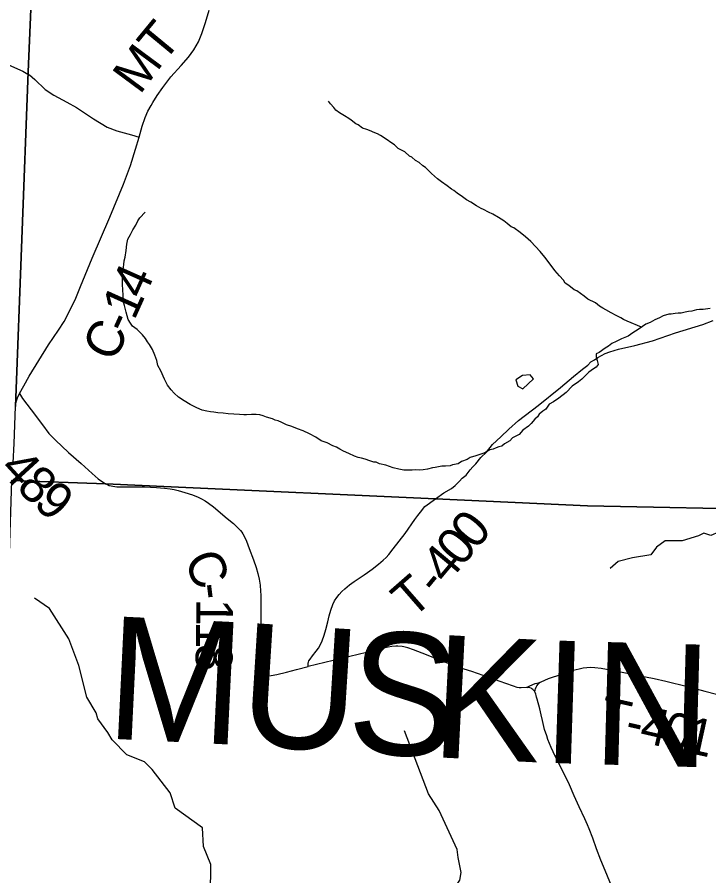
# Model space of a CAD drawing. Extents: x 0 to 34, y 0 to 22.
# Drawn here: x 26.261 to 27.33, y 17.319 to 18.646 of the extents above; entities that cross this region are included whole.
import ezdxf

# ---------------------------------------------------------------- set-up
doc = ezdxf.new("R2010")
doc.units = 0
for name, color, linetype in [('GM_X_Adjacent_County', 7, 'Continuous'), ('GM_X_Adjacent_County_Text', 7, 'Continuous'), ('GM_X_County', 7, 'Continuous'), ('GM_X_County_Road', 7, 'Continuous'), ('GM_X_County_Road_Text', 7, 'Continuous'), ('GM_X_Minor_Lake', 7, 'Continuous'), ('GM_X_Minor_River', 7, 'Continuous'), ('GM_X_Township', 7, 'Continuous'), ('GM_X_Township_Road', 7, 'Continuous'), ('GM_X_Township_Road_Text', 7, 'Continuous')]:
    doc.layers.add(name, color=color, linetype=linetype)

msp = doc.modelspace()

# ---------------------------------------------------------------- linework, layer by layer
at = {"layer": 'GM_X_Adjacent_County'}
for points in [[(29.1279, 17.8574), (28.6324, 17.8677), (28.1264, 17.8728), (27.8903, 17.8826), (27.7531, 17.8783), (27.1422, 17.8906), (26.9072, 17.9017), (26.4988, 17.9198), (26.3979, 17.9244), (26.2521, 17.9299)], [(26.2521, 17.9299), (26.3979, 17.9244), (26.4988, 17.9198), (26.9072, 17.9017), (27.1422, 17.8906), (27.7531, 17.8783), (27.8903, 17.8826), (28.1264, 17.8728), (28.6324, 17.8677), (29.1279, 17.8574)]]:
    msp.add_lwpolyline(points, dxfattribs=at)
at = {"layer": 'GM_X_County'}
for points in [[(26.2521, 17.9299), (26.3979, 17.9244), (26.4988, 17.9198), (26.9072, 17.9017), (27.1422, 17.8906), (27.7531, 17.8783), (27.8903, 17.8826), (28.1264, 17.8728), (28.6324, 17.8677), (29.1279, 17.8574)], [(29.1279, 17.8574), (28.6324, 17.8677), (28.1264, 17.8728), (27.8903, 17.8826), (27.7531, 17.8783), (27.1422, 17.8906), (26.9072, 17.9017), (26.4988, 17.9198), (26.3979, 17.9244), (26.2521, 17.9299)]]:
    msp.add_lwpolyline(points, dxfattribs=at)
at = {"layer": 'GM_X_County_Road'}
for points in [[(26.2645, 18.0641), (26.2708, 18.0762), (26.2794, 18.0911), (26.3092, 18.1395), (26.3247, 18.1621), (26.3335, 18.1754), (26.3418, 18.1917), (26.3512, 18.2118), (26.3583, 18.2295), (26.3766, 18.2737), (26.404, 18.337), (26.4252, 18.3876), (26.4358, 18.4166), (26.4436, 18.4418), (26.4491, 18.4603), (26.454, 18.4777), (26.4585, 18.4908), (26.4624, 18.5005), (26.4677, 18.5096), (26.4706, 18.5139), (26.4771, 18.5249), (26.4856, 18.5372), (26.4984, 18.5535), (26.5141, 18.5715), (26.5256, 18.5842), (26.5337, 18.5956), (26.5409, 18.6079), (26.5462, 18.6205), (26.552, 18.6379), (26.5576, 18.6567)], [(26.2547, 17.9571), (26.2561, 17.9871), (26.2579, 18.0444), (26.2593, 18.0513), (26.2611, 18.0574), (26.2645, 18.0641)], [(26.2645, 18.0641), (26.2689, 18.0566), (26.2824, 18.0389), (26.2998, 18.016), (26.3095, 18.0024), (26.3197, 17.9919), (26.34, 17.9732), (26.3594, 17.9563), (26.3765, 17.9405), (26.3858, 17.9324), (26.397, 17.9245)], [(26.397, 17.9245), (26.4001, 17.9234), (26.4029, 17.9223), (26.4058, 17.9215), (26.4087, 17.9209), (26.4147, 17.9202), (26.4239, 17.9199), (26.4484, 17.92), (26.4577, 17.9199), (26.4669, 17.9196), (26.4761, 17.9191), (26.4883, 17.9182), (26.4974, 17.917), (26.5035, 17.9159), (26.5096, 17.9145), (26.5197, 17.9115), (26.5315, 17.9076), (26.5402, 17.9041), (26.5458, 17.9015), (26.5513, 17.8984), (26.5565, 17.8949), (26.5639, 17.8892), (26.5853, 17.8713), (26.5948, 17.8633), (26.5994, 17.8592), (26.6039, 17.8548), (26.6059, 17.8524), (26.6078, 17.85), (26.6095, 17.8474), (26.6126, 17.8419), (26.615, 17.8358), (26.6194, 17.8247), (26.626, 17.8071), (26.63, 17.7953), (26.6326, 17.7863), (26.6347, 17.7772), (26.6361, 17.7679), (26.637, 17.7586), (26.6372, 17.7524), (26.6373, 17.743), (26.6375, 17.7369), (26.6374, 17.7245), (26.6373, 17.7121), (26.6368, 17.6998), (26.6364, 17.6905), (26.6362, 17.6813), (26.6357, 17.6657), (26.6351, 17.6534), (26.635, 17.6441), (26.6352, 17.6411), (26.6355, 17.6382), (26.636, 17.6363), (26.6366, 17.6352), (26.6379, 17.6334), (26.6399, 17.6313), (26.6409, 17.6305), (26.642, 17.63), (26.6444, 17.629), (26.6472, 17.6284), (26.6502, 17.628), (26.6532, 17.6283), (26.6622, 17.6301), (26.6772, 17.6337), (26.6922, 17.6377), (26.7104, 17.6423)]]:
    msp.add_lwpolyline(points, dxfattribs=at)
at = {"layer": 'GM_X_Minor_Lake'}
for points in [[(27.0589, 18.0872), (27.0535, 18.0933), (27.0418, 18.0921), (27.0316, 18.0853)], [(27.0316, 18.0853), (27.0343, 18.0754), (27.0422, 18.0716), (27.0589, 18.0872)]]:
    msp.add_lwpolyline(points, dxfattribs=at)
at = {"layer": 'GM_X_Minor_River'}
for points in [[(27.2259, 18.1667), (27.2037, 18.1763), (27.198, 18.1789), (27.1939, 18.1812), (27.1866, 18.1846), (27.1787, 18.1891), (27.1703, 18.1937), (27.1658, 18.1963), (27.1608, 18.1994), (27.1548, 18.2043), (27.1426, 18.2103), (27.1373, 18.2149), (27.1316, 18.219), (27.1255, 18.2232), (27.1217, 18.2247), (27.1134, 18.2311), (27.1077, 18.2349), (27.105, 18.2394), (27.0989, 18.2463), (27.0917, 18.2542), (27.0845, 18.2641), (27.0765, 18.2751), (27.0689, 18.2838), (27.062, 18.2917), (27.0548, 18.2993), (27.0465, 18.3065), (27.0381, 18.3133), (27.0282, 18.3201), (27.0244, 18.322), (27.018, 18.3269), (27.0127, 18.3311), (27.0047, 18.3364), (26.996, 18.3413), (26.9891, 18.3447), (26.9816, 18.3488), (26.9778, 18.3503), (26.9705, 18.3545), (26.9618, 18.3602), (26.9554, 18.3636), (26.9489, 18.3685), (26.9409, 18.3738), (26.9356, 18.3783), (26.9318, 18.3802), (26.9254, 18.3851), (26.9163, 18.3912), (26.9106, 18.3961), (26.9011, 18.4041), (26.8916, 18.4135), (26.8878, 18.4162), (26.8821, 18.4211), (26.8764, 18.4245), (26.8707, 18.4294), (26.8669, 18.4309), (26.8597, 18.4377), (26.8494, 18.443), (26.8441, 18.4487), (26.8399, 18.451), (26.8312, 18.4574), (26.8224, 18.4631), (26.8175, 18.4654), (26.8133, 18.4672), (26.805, 18.471), (26.8012, 18.4721), (26.7944, 18.4744), (26.7879, 18.4793), (26.7841, 18.4812), (26.7769, 18.4869), (26.7731, 18.4892), (26.7667, 18.4933), (26.7587, 18.4982), (26.753, 18.5024), (26.7499, 18.5062), (26.745, 18.5122), (26.742, 18.516)], [(26.8948, 17.9472), (26.888, 17.9461), (26.8823, 17.9457), (26.877, 17.9461), (26.8713, 17.9457), (26.8638, 17.9457), (26.8585, 17.946), (26.8505, 17.9475), (26.8418, 17.9494), (26.8304, 17.9536), (26.8209, 17.9558), (26.8156, 17.9581), (26.8118, 17.9584), (26.8057, 17.96), (26.7985, 17.9626), (26.7929, 17.9641), (26.7879, 17.9652), (26.7822, 17.9675), (26.7735, 17.9716), (26.7652, 17.975), (26.7595, 17.9784), (26.7542, 17.9811), (26.7488, 17.9834), (26.7397, 17.9879), (26.7306, 17.9913), (26.7223, 17.997), (26.7124, 18.0019), (26.7025, 18.0064), (26.6942, 18.0098), (26.6851, 18.0132), (26.6771, 18.0158), (26.6699, 18.0196), (26.6639, 18.0219), (26.6593, 18.023), (26.6551, 18.0249), (26.646, 18.0279), (26.6407, 18.0298), (26.6358, 18.0313), (26.6301, 18.0317), (26.6229, 18.0317), (26.6149, 18.0313), (26.6112, 18.0313), (26.6043, 18.0316), (26.5956, 18.0324), (26.5869, 18.0327), (26.5793, 18.0339), (26.571, 18.0346), (26.5649, 18.0353), (26.5596, 18.0361), (26.5539, 18.0372), (26.5467, 18.0387), (26.5384, 18.0421), (26.5281, 18.0474), (26.5186, 18.0531), (26.5099, 18.0588), (26.5034, 18.0648), (26.4985, 18.0697), (26.4932, 18.0773), (26.4882, 18.0864), (26.4829, 18.0993), (26.4783, 18.1076), (26.4764, 18.1152), (26.4733, 18.1236), (26.4699, 18.1323), (26.4653, 18.1402), (26.4623, 18.144), (26.4589, 18.1493), (26.4543, 18.155), (26.4459, 18.1633), (26.4387, 18.1683), (26.4357, 18.1728), (26.4322, 18.1789), (26.4292, 18.1902), (26.4265, 18.2001), (26.425, 18.2054), (26.4246, 18.2096), (26.4246, 18.216), (26.4238, 18.2248), (26.4234, 18.2324), (26.4233, 18.246), (26.4237, 18.2506), (26.4241, 18.2544), (26.4252, 18.2593), (26.4256, 18.2638), (26.4263, 18.2695), (26.4274, 18.2752), (26.4293, 18.2851), (26.4304, 18.295), (26.4319, 18.3026), (26.4356, 18.3102), (26.4394, 18.3174), (26.4439, 18.3246), (26.447, 18.331), (26.4504, 18.3356), (26.4587, 18.3447)], [(27.3317, 18.1955), (27.3208, 18.194), (27.3151, 18.194), (27.3109, 18.1936), (27.3033, 18.1913), (27.2984, 18.1909), (27.2931, 18.1901), (27.287, 18.1886), (27.2821, 18.1882), (27.2776, 18.1878), (27.2715, 18.1871), (27.2677, 18.1867), (27.2594, 18.1844), (27.2537, 18.181), (27.2462, 18.1779), (27.2393, 18.1741), (27.2325, 18.1714), (27.2272, 18.1676), (27.2204, 18.1631), (27.2125, 18.1581), (27.2053, 18.1528), (27.1947, 18.1486), (27.1864, 18.1444), (27.18, 18.1417), (27.1747, 18.1375), (27.1694, 18.1345), (27.1603, 18.1276), (27.1558, 18.1254), (27.1554, 18.1212), (27.1569, 18.1151), (27.1585, 18.109), (27.1558, 18.1052), (27.1513, 18.1022), (27.1445, 18.0973), (27.1335, 18.0862), (27.1282, 18.0824), (27.1184, 18.0756), (27.1093, 18.0657), (27.098, 18.0573), (27.0897, 18.0516), (27.0829, 18.0478), (27.0776, 18.0402), (27.0734, 18.0368), (27.0674, 18.0322), (27.0647, 18.0284), (27.0609, 18.0246), (27.0553, 18.0181), (27.0511, 18.014), (27.0424, 18.0075), (27.0364, 18.0007), (27.0265, 17.9957), (27.022, 17.9911), (27.0141, 17.9866), (27.0099, 17.9831), (27.0054, 17.982), (27.0012, 17.9801), (26.9963, 17.9782), (26.991, 17.977), (26.9834, 17.9725), (26.9759, 17.9698), (26.9694, 17.9679), (26.9611, 17.9656), (26.9562, 17.9622), (26.9475, 17.9591), (26.9422, 17.9557), (26.9338, 17.9538), (26.9297, 17.9526), (26.9225, 17.9522), (26.9168, 17.9522), (26.9066, 17.9499), (26.9024, 17.9492), (26.8948, 17.9472)], [(27.365, 17.8814), (27.3615, 17.8687), (27.3563, 17.8549), (27.3329, 17.8446), (27.3218, 17.8486), (27.314, 17.8445), (27.2886, 17.8365), (27.2621, 17.8368), (27.2489, 17.8269), (27.2403, 17.8151), (27.2119, 17.8104), (27.1896, 17.8046), (27.1772, 17.794)], [(26.5597, 17.2892), (26.5602, 17.3362), (26.5488, 17.3643), (26.5471, 17.3927), (26.505, 17.4233), (26.4973, 17.4468), (26.4695, 17.4831), (26.4573, 17.4948), (26.43, 17.5057), (26.4076, 17.5288), (26.4007, 17.5402), (26.3855, 17.5614), (26.3828, 17.5708), (26.3683, 17.5951), (26.356, 17.644), (26.3407, 17.6853), (26.3106, 17.7322), (26.2874, 17.7477)], [(26.8399, 16.9945), (26.8418, 17.0014), (26.8315, 17.0177), (26.8303, 17.0374), (26.8352, 17.0469), (26.8487, 17.0595), (26.8668, 17.0986), (26.8869, 17.1662), (26.8948, 17.1887), (26.899, 17.2539), (26.9043, 17.2638), (26.9276, 17.2863), (26.9449, 17.3118), (26.9468, 17.3239), (26.9425, 17.347), (26.9406, 17.3595), (26.9127, 17.4198), (26.8967, 17.4455), (26.8591, 17.5429)]]:
    msp.add_lwpolyline(points, dxfattribs=at)
at = {"layer": 'GM_X_Township'}
for points in [[(26.2579, 18.0444), (26.2775, 18.5614), (26.3204, 19.5672), (26.3254, 19.7889), (26.3235, 19.7961), (26.3228, 19.8045), (26.3228, 19.8154), (26.3238, 19.8473), (26.3245, 19.8669), (26.325, 19.9211), (26.326, 19.9813), (26.3403, 20.3674), (26.341, 20.3982), (26.344, 20.4298), (26.3517, 20.745), (26.352, 20.7571), (26.3529, 20.7844), (26.3538, 20.8148), (26.354, 20.8204), (26.3551, 20.8572), (26.3564, 20.9)], [(26.3564, 20.9), (26.3551, 20.8572), (26.354, 20.8204), (26.3538, 20.8148), (26.3529, 20.7844), (26.352, 20.7571), (26.3517, 20.745), (26.344, 20.4298), (26.341, 20.3982), (26.3403, 20.3674), (26.326, 19.9813), (26.325, 19.9211), (26.3245, 19.8669), (26.3238, 19.8473), (26.3228, 19.8154), (26.3228, 19.8045), (26.3235, 19.7961), (26.3254, 19.7889), (26.3204, 19.5672), (26.2775, 18.5614), (26.2579, 18.0444)], [(30.8167, 17.8174), (30.1304, 17.8301), (29.8296, 17.8449), (29.1279, 17.8574), (28.6324, 17.8677), (28.1264, 17.8728), (27.8903, 17.8826), (27.7531, 17.8783), (27.1422, 17.8906), (26.9072, 17.9017), (26.4988, 17.9198), (26.3979, 17.9244), (26.2521, 17.9299), (26.228, 17.2045)], [(26.2521, 17.9299), (26.3979, 17.9244), (26.4988, 17.9198), (26.9072, 17.9017), (27.1422, 17.8906), (27.7531, 17.8783), (27.8903, 17.8826), (28.1264, 17.8728), (28.6324, 17.8677), (29.1279, 17.8574)]]:
    msp.add_lwpolyline(points, dxfattribs=at)
at = {"layer": 'GM_X_Township_Road'}
for points in [[(26.2471, 18.5723), (26.2695, 18.5625), (26.2773, 18.5581), (26.2799, 18.5566), (26.2881, 18.5497)], [(26.2881, 18.5497), (26.2882, 18.5497), (26.3041, 18.5344), (26.3171, 18.5253), (26.3374, 18.5144), (26.3524, 18.5062), (26.3645, 18.4981), (26.3784, 18.4886), (26.3999, 18.476), (26.4146, 18.4702), (26.4375, 18.464), (26.4491, 18.4603)], [(26.9072, 17.9017), (26.9204, 17.9108), (26.9322, 17.9173), (26.9376, 17.9222), (26.9445, 17.9287), (26.9487, 17.9332), (26.9547, 17.938), (26.9611, 17.9464), (26.9651, 17.9511), (26.9698, 17.9558), (26.9775, 17.9655), (26.986, 17.9737), (26.9956, 17.9854), (27.0083, 17.9975), (27.0207, 18.0092), (27.0356, 18.0224), (27.0657, 18.0455), (27.1004, 18.0733), (27.1205, 18.0907), (27.1347, 18.1021), (27.1429, 18.1083), (27.1476, 18.113), (27.1528, 18.1162), (27.1583, 18.1197), (27.1638, 18.1229), (27.1695, 18.1262), (27.1767, 18.1289), (27.1901, 18.1329), (27.2154, 18.1383), (27.2427, 18.1455), (27.278, 18.158), (27.3207, 18.1711), (27.3363, 18.1771)], [(26.7104, 17.6423), (26.7103, 17.6462), (26.7104, 17.6478), (26.7109, 17.6492), (26.7117, 17.6513), (26.7134, 17.6537), (26.7171, 17.6586), (26.7228, 17.6659), (26.7263, 17.6709), (26.7293, 17.6763), (26.7319, 17.6819), (26.7351, 17.6906), (26.7378, 17.6994), (26.7408, 17.7114), (26.7429, 17.7204), (26.7457, 17.7292), (26.7488, 17.7379), (26.7514, 17.7436), (26.7546, 17.7489), (26.7583, 17.7538), (26.7625, 17.7583), (26.7671, 17.7625), (26.7743, 17.7683), (26.7818, 17.7737), (26.7971, 17.784), (26.8021, 17.7875), (26.8096, 17.793), (26.8194, 17.8005), (26.8265, 17.8065), (26.8309, 17.8109), (26.835, 17.8155), (26.8416, 17.8241), (26.8604, 17.8481), (26.8754, 17.8697), (26.88, 17.8756), (26.8841, 17.8808), (26.8909, 17.8896), (26.9072, 17.9017)], [(27.0484, 17.6098), (27.048, 17.6098), (27.0397, 17.6093), (27.0366, 17.6095), (27.0336, 17.61), (27.0276, 17.6117), (27.0159, 17.6158), (26.9633, 17.6344), (26.9515, 17.6383), (26.9339, 17.6444), (26.9136, 17.6522), (26.8935, 17.6602), (26.8733, 17.6683), (26.8645, 17.6713), (26.8585, 17.6729), (26.8555, 17.6734), (26.8493, 17.6738), (26.8462, 17.6737), (26.84, 17.6731), (26.8339, 17.672), (26.8248, 17.67), (26.8008, 17.6638), (26.7104, 17.6423)], [(27.0689, 17.618), (27.0705, 17.6187), (27.0819, 17.6235), (27.1025, 17.6306), (27.1202, 17.6364), (27.1292, 17.6389), (27.1353, 17.6401), (27.1414, 17.6409), (27.1476, 17.6411), (27.1538, 17.6408), (27.1631, 17.6397), (27.1905, 17.6345), (27.221, 17.6284), (27.2453, 17.6237), (27.2635, 17.6196), (27.2966, 17.6114), (27.3237, 17.6043), (27.3417, 17.5996)], [(27.0484, 17.6098), (27.0502, 17.611), (27.0519, 17.6118), (27.0533, 17.6124), (27.0615, 17.6158), (27.0639, 17.6165), (27.0664, 17.6172), (27.0689, 17.618)], [(27.0608, 17.603), (27.0611, 17.6053), (27.0613, 17.6067), (27.0616, 17.6078), (27.0628, 17.6106), (27.0639, 17.6124), (27.0657, 17.6149), (27.0669, 17.6162), (27.0677, 17.6169), (27.0689, 17.618)], [(27.0608, 17.603), (27.0601, 17.6042), (27.0589, 17.6057), (27.0577, 17.6068), (27.0562, 17.6078), (27.0549, 17.6086), (27.0529, 17.6093), (27.0509, 17.6098), (27.0484, 17.6098)], [(27.1777, 17.3067), (27.172, 17.3209), (27.1626, 17.3429), (27.1562, 17.3605), (27.1504, 17.3768), (27.1448, 17.3914), (27.1424, 17.3976), (27.138, 17.407), (27.1292, 17.4254), (27.1217, 17.4424), (27.1143, 17.4595), (27.1077, 17.4735), (27.0921, 17.5036), (27.086, 17.5172), (27.081, 17.5294), (27.0792, 17.5351), (27.076, 17.5447), (27.0727, 17.5588), (27.0705, 17.5678), (27.0684, 17.5768), (27.0644, 17.5918), (27.0635, 17.5949), (27.0628, 17.5974), (27.0622, 17.5994), (27.0613, 17.602), (27.0608, 17.603)]]:
    msp.add_lwpolyline(points, dxfattribs=at)

# ---------------------------------------------------------------- texts
at = {"layer": 'GM_X_Adjacent_County_Text'}
for s, rotation, p in [('M', 357.2115, (26.3958, 17.5311)), ('U', 356.4278, (26.6007, 17.5211)), ('S', 356.4112, (26.7679, 17.5107)), ('K', 357.0853, (26.8984, 17.5025)), ('I', 358.1377, (27.0695, 17.4938)), ('N', 358.4214, (27.148, 17.4913))]:
    msp.add_text(s, height=0.1894, rotation=rotation, dxfattribs=at).set_placement(p)
at = {"layer": 'GM_X_County_Road_Text'}
for s, rotation, p in [('T', 50.454, (26.4865, 18.5738)), ('M', 53.4916, (26.4503, 18.5249)), ('4', 65.8802, (26.4561, 18.2081)), ('1', 65.7626, (26.4416, 18.1761)), ('-', 65.4829, (26.4318, 18.1546)), ('C', 62.9462, (26.4094, 18.1105)), ('4', 312.5205, (26.2311, 17.9463)), ('8', 316.1886, (26.2575, 17.9176)), ('9', 317.633, (26.2839, 17.8923)), ('C', 293.1489, (26.5178, 17.8075)), ('-', 276.9798, (26.5351, 17.7687)), ('1', 269.3182, (26.5378, 17.7475)), ('1', 269.1881, (26.5374, 17.7125)), ('8', 269.1777, (26.5369, 17.6776))]:
    msp.add_text(s, height=0.0568, rotation=rotation, dxfattribs=at).set_placement(p)
at = {"layer": 'GM_X_Township_Road_Text'}
for s, rotation, p in [('0', 50.0213, (26.9693, 17.8209)), ('0', 50.0178, (26.9469, 17.7943)), ('4', 49.9936, (26.9246, 17.7677)), ('T', 41.1158, (26.8709, 17.7147)), ('-', 50.5673, (26.91, 17.7499)), ('T', 347.0719, (27.1563, 17.5412)), ('4', 347.1127, (27.2205, 17.5265)), ('0', 347.2214, (27.2547, 17.5186)), ('1', 347.5961, (27.2893, 17.5108)), ('-', 347.0752, (27.1977, 17.5317))]:
    msp.add_text(s, height=0.0568, rotation=rotation, dxfattribs=at).set_placement(p)

doc.saveas('drawing.dxf')
